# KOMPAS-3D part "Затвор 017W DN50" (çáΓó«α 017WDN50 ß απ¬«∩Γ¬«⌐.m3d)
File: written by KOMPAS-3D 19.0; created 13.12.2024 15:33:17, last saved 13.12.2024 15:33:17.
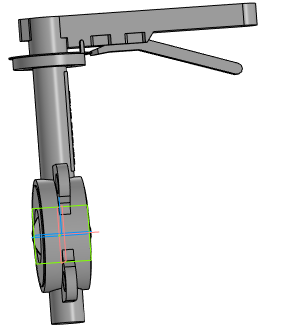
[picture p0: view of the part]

Document properties: Автор: Евгений; Полное имя файла: ..\Затвор 017WDN50.a3d

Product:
- Part/product: Затвор 017W DN50
    Масса: 4.72614

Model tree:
1. Операция без истории:1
